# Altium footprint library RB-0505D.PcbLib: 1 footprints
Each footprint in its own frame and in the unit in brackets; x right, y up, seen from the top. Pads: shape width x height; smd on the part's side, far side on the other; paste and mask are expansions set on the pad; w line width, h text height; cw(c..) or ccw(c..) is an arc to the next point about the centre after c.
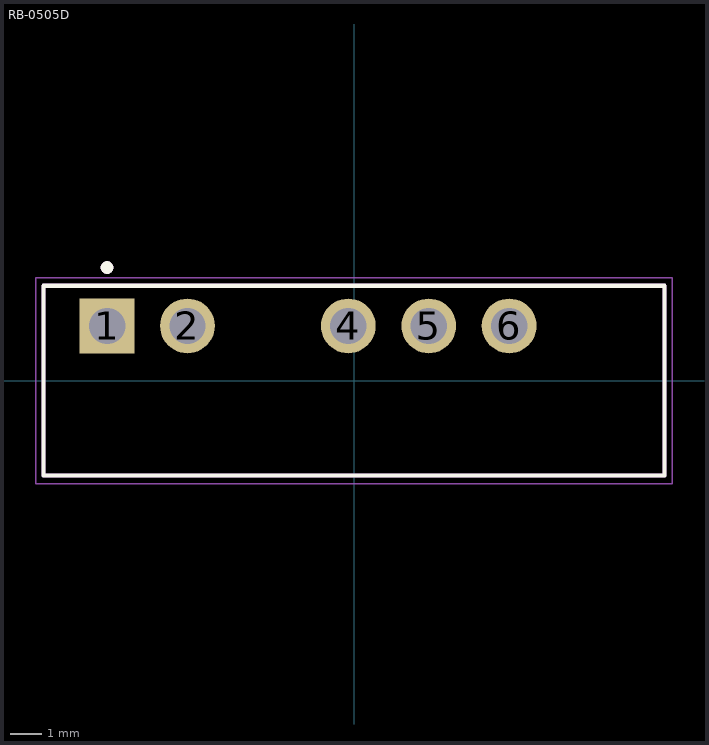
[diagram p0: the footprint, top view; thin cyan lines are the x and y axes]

## RB-0505D [mm]
height 10.2
pads (5):
  rect 1.73x1.73 / inner round 1.73 / far side rect 1.73x1.73 hole 1.15: 1(-7.8,1.73)
  round 1.73 hole 1.15: 2(-5.26,1.73) 4(-0.18,1.73) 5(2.36,1.73) 6(4.9,1.73)
Top Overlay:
  circle w0.2: c-7.8,3.575 r0.1
  lines w0.127: -9.8,-3 -9.8,3 9.8,3 9.8,-3 -9.8,-3
Mechanical 13:
  circle w0.2: c-7.8,3.575 r0.1
  lines w0.127: -9.8,-3 -9.8,3 9.8,3 9.8,-3 -9.8,-3
Mechanical 15:
  lines w0.05: -10.05,-3.25 -10.05,3.25 10.05,3.25 10.05,-3.25 -10.05,-3.25
3D body "RB-0505D.STEP": height 10.18, standoff -3.1, extent -9.835,-2.917 9.765,3.083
